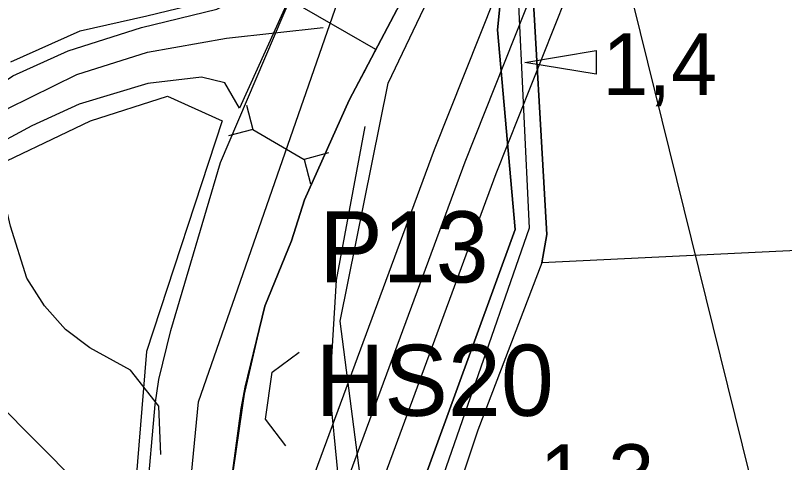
# Model space of a CAD drawing. Extents: x -684583 to -680383, y -1157874 to -1154904.
# Drawn here: x -683203.8 to -683041.8, y -1157172.5 to -1157078.2 of the extents above; entities that cross this region are included whole.
import ezdxf

# ---------------------------------------------------------------- set-up
doc = ezdxf.new("R2010")
doc.units = 0
for name, color, linetype in [('01_DOPRAVA', 7, 'Continuous'), ('01_PRVKY PRŮZKUMU', 7, 'Continuous'), ('01_VRSTEVNICE', 7, 'Continuous'), ('02_KULTURY STAV', 7, 'Continuous'), ('03_PC_OBJEKTY_STAV', 7, 'Continuous'), ('04_ZPF_OP_ORGAN', 7, 'Continuous'), ('05_VHO_V_TOK', 7, 'Continuous'), ('06_BIOGEOGRAFIE', 7, 'Continuous'), ('06_ÚSES_BK', 7, 'Continuous'), ('07_ELEKTRO', 7, 'Continuous'), ('07_OCH_P A POPISY TI', 7, 'Continuous')]:
    doc.layers.add(name, color=color, linetype=linetype)

msp = doc.modelspace()

# ---------------------------------------------------------------- linework, layer by layer
at = {"layer": '01_DOPRAVA'}
for points in [[(-683054.51, -1157758.92), (-683045.66, -1157702.14), (-683033.32, -1157625.99), (-683033.32, -1157571.3), (-683045.07, -1157508.09), (-683105.62, -1157372.25), (-683148.82, -1157294.04), (-683163.81, -1157254.05), (-683168.81, -1157196.71), (-683165.28, -1157159.67), (-683135.89, -1157075.28), (-683079.46, -1156981.49), (-683035.96, -1156902.98), (-682993.94, -1156817.72), (-682972.78, -1156716.87), (-682952.5, -1156631.31), (-682921.05, -1156497.23), (-682883.43, -1156372.57), (-682870.79, -1156344.34), (-682802.61, -1156200.56), (-682782.62, -1156147.93)], [(-683848.9, -1157421.35), (-683768.73, -1157372.16), (-683751.13, -1157356.37), (-683692.43, -1157298.55), (-683668.13, -1157274.02), (-683656.09, -1157268.45), (-683636.34, -1157266.75), (-683560.15, -1157260.5), (-683520.41, -1157256.3), (-683504.28, -1157253.8), (-683468.06, -1157246.75), (-683377.9, -1157224.15), (-683360.31, -1157216.54), (-683346.34, -1157208.36), (-683325.33, -1157193.59), (-683264.93, -1157143.95), (-683216.9, -1157105.1), (-683205.43, -1157097.83), (-683190.89, -1157090.67), (-683176.02, -1157086.02), (-683159.33, -1157083.06), (-683139, -1157080.79)]]:
    msp.add_lwpolyline(points, dxfattribs=at)
at = {"layer": '01_PRVKY PRŮZKUMU'}
for points in [[(-683204.8, -1157088.06), (-683190.17, -1157081.47), (-683176.15, -1157078.3), (-683161.03, -1157074.64), (-683143.11, -1157062.81), (-683112.27, -1157011.21), (-683178.47, -1156970.96), (-683199.16, -1156972.48), (-683204.37, -1156977.31)], [(-683079.01, -1157360), (-683101.29, -1157316.95), (-683114.85, -1157271.95), (-683118.75, -1157234.34), (-683126.76, -1157209.48), (-683135.39, -1157142.69), (-683125.32, -1157092.55), (-683090.58, -1157019.64), (-682963.99, -1157096.18), (-682973.33, -1157242.9), (-682974.69, -1157258.59), (-682742.08, -1157344.31)]]:
    msp.add_lwpolyline(points, dxfattribs=at)
at = {"layer": '01_VRSTEVNICE'}
for points in [[(-683173.18, -1157170.81), (-683173.59, -1157160.59), (-683179.58, -1157153.03), (-683188.14, -1157148.33), (-683193.28, -1157144.47), (-683197.7, -1157139.48), (-683201.41, -1157133.63), (-683204.83, -1157122.65), (-683208.25, -1157108.1), (-683211.82, -1157098.4), (-683213.96, -1157095.4), (-683215.39, -1157094.83), (-683215.39, -1157093.98), (-683243.06, -1157080.57), (-683253.19, -1157073.15), (-683274.16, -1157050.9), (-683283.57, -1157042.34), (-683292.84, -1157035.78), (-683302.97, -1157030.22), (-683323.65, -1157022.66), (-683338.2, -1157016.38), (-683364.45, -1157002.97), (-683378.14, -1156999.26)], [(-683130.23, -1157101.68), (-683136.22, -1157134.06), (-683137.65, -1157157.17), (-683135.93, -1157175.14), (-683128.52, -1157208.52), (-683126.96, -1157221.89), (-683127.09, -1157233.2)], [(-683237.35, -1157107.1), (-683228.65, -1157118.94), (-683225.66, -1157132.63), (-683221.23, -1157141.76), (-683213.39, -1157152.89), (-683207.83, -1157159.59), (-683190.71, -1157176.85), (-683186.29, -1157183.7), (-683183.01, -1157192.83), (-683180.15, -1157211.09), (-683174.45, -1157232.63)]]:
    msp.add_lwpolyline(points, dxfattribs=at)
at = {"layer": '02_KULTURY STAV'}
for points in [[(-683204.36, -1157091.01), (-683192.73, -1157085.68), (-683177.22, -1157080.76), (-683161.41, -1157076.94), (-683151.59, -1157072.03), (-683141.73, -1157064.85), (-683126.11, -1157041.1), (-683133.89, -1157037.59), (-683152.2, -1157026.98), (-683160.47, -1157023.44), (-683170.17, -1157021.68), (-683173.51, -1157019.17), (-683179.14, -1157002.96), (-683179.35, -1156991.49), (-683183.38, -1156982.14), (-683189.82, -1156979.08), (-683195.45, -1156980.19), (-683203.65, -1156985.03), (-683213.41, -1156987.19)], [(-683120.11, -1157182.61), (-683098.55, -1157123.33), (-683102.28, -1157081.27), (-683101.23, -1157070.84), (-683104.68, -1157057.95), (-683110.2, -1157052.54), (-683104.87, -1157044.75), (-683100.2, -1157050.38), (-683095.49, -1157062.13), (-683091.87, -1157124.45), (-683092.93, -1157130.42), (-683106.43, -1157165.69), (-683118.57, -1157201.97)], [(-683158.62, -1157178.84), (-683156.25, -1157161.12), (-683155.4, -1157156.58), (-683151.27, -1157139.55), (-683145.65, -1157125.76), (-683142.92, -1157117.14), (-683133.51, -1157096.13), (-683121.44, -1157073.16), (-683110.2, -1157052.54), (-683104.68, -1157057.95), (-683101.69, -1157067.24), (-683101.23, -1157070.84), (-683102.28, -1157081.27), (-683098.55, -1157123.33), (-683120.11, -1157182.61)], [(-683333.9, -1157194.91), (-683303.88, -1157170.13), (-683264.09, -1157137.63), (-683247.5, -1157123.53), (-683236.68, -1157113.93), (-683234.11, -1157111.74), (-683231.81, -1157109.78), (-683221.99, -1157102.98), (-683204.36, -1157091.01), (-683192.73, -1157085.68), (-683177.22, -1157080.76), (-683161.41, -1157076.94), (-683151.59, -1157072.03), (-683141.73, -1157064.85), (-683156.58, -1157097.8), (-683159.7, -1157092.45), (-683164.59, -1157091.26), (-683175.94, -1157092.6), (-683190.37, -1157096.97), (-683200.33, -1157101.53), (-683210.06, -1157106.68), (-683242.35, -1157132.43), (-683297.96, -1157177.33)]]:
    msp.add_lwpolyline(points, dxfattribs=at)
for points in [[(-683104.87, -1157044.75), (-683097.43, -1157031.94), (-683090.58, -1157019.64), (-683072.43, -1156988.22), (-683068.4, -1156989.49), (-683064.02, -1156992.6), (-683069.65, -1157008.14), (-683071.62, -1157014.89), (-683071.88, -1157022.44), (-683071.15, -1157028.51), (-683069.3, -1157031.54), (-683062.84, -1157036.11), (-683044.54, -1157047.31), (-683026.78, -1157057.53), (-683003.8, -1157070.41), (-682984.94, -1157081.43), (-682973.97, -1157087.66), (-682964.52, -1157092.89), (-682957.27, -1157088.26), (-682958.06, -1157123.89), (-683092.93, -1157130.42), (-683091.87, -1157124.45), (-683095.49, -1157062.13), (-683100.2, -1157050.38)], [(-683177.86, -1157201.14), (-683176.16, -1157180.18), (-683176.16, -1157180.18), (-683174.37, -1157160.26), (-683173.62, -1157154.95), (-683171.05, -1157144.64), (-683171.05, -1157144.64), (-683160.6, -1157109.21), (-683160.6, -1157109.21), (-683141.73, -1157064.85), (-683126.11, -1157041.1), (-683110.2, -1157052.54), (-683121.44, -1157073.16), (-683133.51, -1157096.13), (-683142.92, -1157117.14), (-683145.65, -1157125.76), (-683151.27, -1157139.55), (-683155.4, -1157156.58), (-683158.62, -1157178.84), (-683158.11, -1157200.75), (-683157.35, -1157217.4)], [(-683092.93, -1157130.42), (-683106.43, -1157165.69), (-683118.57, -1157201.97), (-683120.22, -1157223.29), (-683120.73, -1157236.27), (-683120.05, -1157251.32), (-683117.34, -1157269.31), (-683109.5, -1157295.71), (-683104.67, -1157310.58), (-683097.47, -1157329.16), (-683089.13, -1157345.4), (-683079.01, -1157360), (-683060.22, -1157384.58), (-683050.32, -1157398.08), (-682970.5, -1157367.3), (-682967.98, -1157337.6), (-682967.71, -1157306.5), (-682965.68, -1157276.1), (-682963.63, -1157251.67), (-682961.95, -1157195.51), (-682958.06, -1157123.89)]]:
    msp.add_lwpolyline(points, close=True, dxfattribs=at)
at = {"layer": '03_PC_OBJEKTY_STAV'}
for points in [[(-683155.13, -1157097.17), (-683153.78, -1157102.3), (-683158.9, -1157103.65)], [(-683153.78, -1157102.3), (-683142.98, -1157108.59)], [(-683137.85, -1157107.24), (-683142.98, -1157108.59), (-683141.63, -1157113.72)], [(-683146.87, -1157168.99), (-683151.13, -1157163.34), (-683149.73, -1157153.44), (-683144.08, -1157149.19)]]:
    msp.add_lwpolyline(points, dxfattribs=at)
at = {"layer": '04_ZPF_OP_ORGAN'}
msp.add_lwpolyline([(-683343.12, -1157216.48), (-683255.77, -1157147.12), (-683212.14, -1157111.99), (-683188, -1157100.46), (-683171.81, -1157095.24), (-683160.28, -1157100.46), (-683176.2, -1157149.05), (-683182.23, -1157222.89), (-683169.61, -1157275.32), (-683083.46, -1157449.64), (-683050.81, -1157531.17), (-683043.68, -1157605.57), (-683055.75, -1157649.76), (-683061.24, -1157640.16), (-683077.15, -1157575.37), (-683110.35, -1157581.68), (-683135.87, -1157597.03), (-683152.6, -1157616.55), (-683323.54, -1157289.05), (-683339.45, -1157238.26)], close=True, dxfattribs=at)
at = {"layer": '05_VHO_V_TOK'}
msp.add_lwpolyline([(-683378.73, -1156994.28), (-683361.67, -1156998.74), (-683352.07, -1156989.61), (-683342.95, -1156971), (-683334.18, -1156973.73), (-683324.11, -1156981.32), (-683316.17, -1156975.87), (-683302.3, -1156964.48), (-683279.9, -1156970.88), (-683268.64, -1156977.76), (-683256.2, -1156986.41), (-683238.07, -1156986.41), (-683206.55, -1156982.5), (-683191.86, -1156974.2), (-683180.36, -1156978.71), (-683174.44, -1156992.7), (-683172.9, -1157010.12), (-683165.9, -1157018.9), (-683149.43, -1157022.45), (-683104.87, -1157050.79), (-683100.25, -1157059.8), (-683098, -1157072.96), (-683095.63, -1157123.11), (-683121.58, -1157197.8)], dxfattribs=at)
msp.add_lwpolyline([(-683081.52, -1157085.66), (-683081.52, -1157090.66), (-683096.52, -1157088.16)], close=True, dxfattribs=at)
at = {"layer": '06_BIOGEOGRAFIE'}
for points in [[(-683605.53, -1156693.94), (-683552.15, -1156773.17), (-683505.66, -1156862.74), (-683385.12, -1156876.52), (-683240.48, -1156867.91), (-682983.91, -1156935.09), (-682923.69, -1156998.38), (-682921.97, -1157094.84), (-682923.69, -1157198.19), (-682892.7, -1157272.26), (-682746.33, -1157329.1), (-682572.41, -1157337.72), (-682417.44, -1157289.49), (-682386.73, -1157266.62)], [(-683662.04, -1156787.77), (-683658.6, -1156877.34), (-683631.05, -1156927.29), (-683541.5, -1156975.52), (-683489.85, -1157028.92), (-683414.08, -1157027.2), (-683362.42, -1157025.48), (-683360.7, -1157063.37), (-683464.02, -1157132.27), (-683493.29, -1157163.28), (-683474.35, -1157189.11), (-683407.19, -1157171.89), (-683317.65, -1157115.05), (-683269.44, -1157104.71), (-683207.44, -1157173.61), (-683186.78, -1157259.74), (-683105.85, -1157416.48), (-683069.69, -1157530.17), (-683073.13, -1157580.12), (-683097.24, -1157628.35), (-683264.27, -1157657.63), (-683431.3, -1157647.3), (-683531.17, -1157605.96), (-683636.21, -1157542.23), (-683651.71, -1157521.56), (-683682.7, -1157519.83), (-683708.53, -1157528.45), (-683818.74, -1157547.39), (-683870.4, -1157518.11), (-683980.6, -1157521.56), (-684052.92, -1157490.55), (-684171.74, -1157400.98), (-684213.07, -1157375.14), (-684250.95, -1157388.92), (-684249.23, -1157437.15), (-684237.17, -1157466.44), (-684170.02, -1157518.11), (-684097.7, -1157562.9), (-684011.6, -1157605.96), (-683953.05, -1157602.51), (-683891.06, -1157626.63), (-683835.96, -1157619.74), (-683789.47, -1157599.07), (-683713.7, -1157578.4), (-683625.88, -1157592.18), (-683551.84, -1157667.97), (-683445.07, -1157736.87), (-683346.92, -1157771.32), (-683179.89, -1157767.87), (-683081.74, -1157773.04), (-683016.71, -1157810.65), (-682999.16, -1157844)]]:
    msp.add_spline(points, degree=3, dxfattribs=at)
at = {"layer": '06_ÚSES_BK'}
for points in [[(-683204.37, -1156977.31), (-683198.55, -1156972.1), (-683188.2, -1156970.02), (-683179.57, -1156969.88), (-683163.5, -1156966.86), (-683140.78, -1156972.01), (-683108.9, -1157008.94), (-683090.58, -1157019.64), (-683082.97, -1157038.32), (-683043.1, -1157199.78)], [(-683158.62, -1157178.84), (-683156.25, -1157161.12), (-683151.27, -1157139.55), (-683145.65, -1157125.76), (-683142.92, -1157117.14), (-683133.51, -1157096.13), (-683130.44, -1157090.32), (-683127.87, -1157085.44), (-683146.23, -1157074.82), (-683146.88, -1157076.28), (-683149.7, -1157070.65), (-683281.53, -1156986.77), (-683319.75, -1156985.6), (-683331.68, -1156983.88), (-683343.69, -1156981.37), (-683347.61, -1156993.23), (-683349.45, -1156999.14), (-683352.15, -1157001.15), (-683359.7, -1157003.17), (-683367.03, -1157002.46), (-683370.86, -1157001.24)]]:
    msp.add_lwpolyline(points, dxfattribs=at)
at = {"layer": '07_ELEKTRO'}
msp.add_lwpolyline([(-683353.35, -1157770.3), (-683109.07, -1157109.08), (-683073.5, -1157019.42), (-683054.68, -1156978.22), (-683011.49, -1156911.63), (-683020.57, -1156816.29), (-682818.44, -1155857.57), (-682314.17, -1155533.82)], dxfattribs=at)
msp.add_lwpolyline([(-683353.35, -1157770.3), (-683109.07, -1157109.08), (-683073.5, -1157019.42), (-683054.68, -1156978.22), (-683011.49, -1156911.63), (-683020.57, -1156816.29), (-682818.44, -1155857.57), (-682314.17, -1155533.82)], dxfattribs=at)
at = {"layer": '07_OCH_P A POPISY TI'}
for p, q in [((-683079.94, -1157016.67), (-683115.61, -1157106.58)), ((-683102.53, -1157111.58), (-683068.97, -1157026.98)), ((-683115.61, -1157106.58), (-683359.92, -1157767.87)), ((-683346.78, -1157772.73), (-683102.53, -1157111.58))]:
    msp.add_line(p, q, dxfattribs=at)

# ---------------------------------------------------------------- texts
at = {"layer": '03_PC_OBJEKTY_STAV'}
for s, p in [('P13', (-683139.82, -1157134.53)), ('HS20', (-683140.59, -1157162.64))]:
    msp.add_text(s, height=15, dxfattribs=at).set_placement(p)
at = {"layer": '05_VHO_V_TOK'}
for s, p in [('1,4', (-683080.2, -1157094.99)), ('1,3', (-683093.41, -1157181.63))]:
    msp.add_text(s, height=13, dxfattribs=at).set_placement(p)

doc.saveas('drawing.dxf')
